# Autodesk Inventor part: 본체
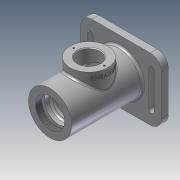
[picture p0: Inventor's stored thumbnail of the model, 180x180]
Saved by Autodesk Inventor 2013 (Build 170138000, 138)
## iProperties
Created: 2021-07
Part Number: 본체
Material: 알루미늄 6061
Document SubType Name: Modeling
Designer: 19
Density: 2.71 g/cm^3
Mass: 742.646 g
Surface Area: 651.172 cm^2
Volume: 274.039 cm^3
Author: 19
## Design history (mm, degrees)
sketch "스케치1"
  geometry: L1 (-57.5, 0)-(57.5, 0); L2 (-57.5, 0)-(-57.5, 31); L3 (-57.5, 31)-(57.5, 31); L4 (57.5, 31)-(57.5, 0); L5 (-57.5, 21)-(-48.5, 21); L6 (-48.5, 21)-(-48.5, 24); L7 (-48.5, 24)-(-45.5, 24); L8 (-45.5, 24)-(-45.5, 20); L9 (-45.5, 20)-(-36.5, 20); L10 (-36.5, 20)-(-36.5, 17.5); L11 (-36.5, 17.5)-(-33.25, 17.5); L12 (-33.25, 17.5)-(-33.25, 18.5); L13 (-33.25, 18.5)-(-31.5, 18.5); L14 (-31.5, 18.5)-(-31.5, 17.5); L15 (-31.5, 17.5)-(-20.5, 17.5); L16 (-20.5, 17.5)-(-20.5, 26); L17 (-20.5, 26)-(17.5, 26); L18 (17.5, 26)-(17.5, 17.5); L19 (17.5, 17.5)-(28.5, 17.5); L20 (28.5, 17.5)-(28.5, 16); L21 (28.5, 16)-(33.5, 16); L22 (33.5, 16)-(33.5, 10); L23 (33.5, 10)-(36.2, 10); L24 (36.2, 10)-(36.2, 12.5); L25 (36.2, 12.5)-(43.5, 12.5); L26 (43.5, 12.5)-(57.5, 22); 2 further points
  constraints: 52 end point, 12 parallel, 12 perpendicular, 2 point on line, 1 coincident, 1 horizontal, 1 midpoint
  dimensions: "d0" = 115 distance of L1.start L1.end; "d1" = 62 diameter of L3 L1; "d2" = 9 distance of L5.start L5.end; "d3" = 3 distance of L6.end L7.end; "d4" = 9 distance of L8.end L9.end; "d5" = 38 distance of L16.end L17.end; "d6" = 11 distance of L14.end L15.end; "d7" = 11 distance of L18.end L19.end; "d8" = 1.75 distance of L12.end L13.end; "d9" = 65 distance of L19.end L10.end; "d10" = 91 horizontal distance of L21.end L5.start; "d11" = 14 horizontal distance of L25.end L26.end; "d12" = 7.3 distance of L24.end L25.end; "d13" = 42 diameter of L5 L1; "d14" = 40 diameter of L9 L1; "d15" = 48 diameter of L7 L1; "d16" = 35 diameter of L15 L1; "d17" = 35 diameter of L11 L1; "d18" = 37 diameter of L13 L1; "d19" = 52 diameter of L17 L1; "d20" = 35 diameter of L19 L1; "d21" = 32 diameter of L21 L1; "d22" = 20 diameter of L23 L1; "d23" = 25 diameter of L25 L1; "d24" = 44 diameter of L26.end L1
revolve "회전1" sketch "스케치1" stored, may be unused: angle "d25" = 90 deg
node "작업 평면1"
sketch "스케치2"
  geometry: L1 (-58, 45)-(58, 45); L2 (58, 45)-(58, -45); L3 (58, -45)-(-58, -45); L4 (-58, -45)-(-58, 45); L5 (-58, 45)-(58, -45); L6 (58, 45)-(-58, -45); C1 r 31 at (0, 0) reference; 1 further point
  constraints: 12 end point, 2 midpoint, 2 parallel, 1 horizontal, 1 perpendicular
  dimensions: "d27" = 116 distance of L2.end L3.end; "d28" = 90 distance of L1.end L2.end
extrude "돌출1" join sketch "스케치2" distance "d29" = 10; taper "d30" = 0 deg
sketch "스케치3"
  geometry: C1 r 31 at (0, 0) reference; C2 r 35 at (0, 0)
  constraints: 1 centre point, 1 coincident
  dimensions: "d31" = 70 diameter of C2
extrude "돌출2" join sketch "스케치3" stored distance "d32" = 10; taper "d33" = 0 deg
fillet "모깎기1" dims "d34" = 16
sketch "스케치4"
  geometry: L1 (40, 25)-(40, -25); L2 (48, -25)-(48, 25); C1 r 35 at (0, 0) reference; A1 r 4 centre (44, 25) between (40, 25) and (48, 25); A2 r 4 centre (44, -25) between (40, -25) and (48, -25)
  constraints: 4 end point, 4 point on circle, 3 tangent, 2 centre point, 1 parallel
  dimensions: "d35" = 8 diameter of A1; "d36" = 8 diameter of A2; "d37" = 50 distance of A2.centre A1.centre; "d38" = 44 horizontal distance of C1.centre A1.centre; "d39" = 25 vertical distance of A1.centre C1.centre; "d40" = 25 vertical distance of C1.centre A2.centre
extrude "돌출3" cut sketch "스케치4" stored distance "d41" = 10; taper "d42" = 0 deg
node "작업 평면2"
sketch "스케치5"
  geometry: L1 (57.5, 31)-(57.5, -31) reference; L2 (57.5, 31)-(-44.5, 31) reference; C1 r 27 at (1.5, 0); 1 further point
  constraints: 1 centre point, 1 coincident
  dimensions: "d44" = 54 diameter of C1; "d81" = 56 distance from line of L1 point (1.5, 0); "d82" = 31 distance from line of L2 point (1.5, 0)
extrude "돌출4" join sketch "스케치5" stored distance "d45" = 10; taper "d46" = 0 deg
sketch "스케치6"
  geometry: C1 r 27 at (0, 0) reference; C2 r 16 at (0, 0)
  constraints: 1 centre point, 1 coincident
  dimensions: "d47" = 32 diameter of C2
extrude "돌출5" cut sketch "스케치6" stored distance "d49" = 10; taper "d50" = 0 deg
sketch "스케치7"
  geometry: L1 (0, 0)-(0, 22); L2 (0, 0)-(0, -22); C1 r 27 at (0, 0) reference; 2 further points
  constraints: 4 end point, 2 coincident, 1 collinear, 1 vertical
  dimensions: "d51" = 22 distance of L1.start L1.end; "d52" = 22 distance of L1.start L2.end
hole "구멍1" sketch "스케치7" at (0, 22), (0, -22) diameter "d53" = 2.459; stored, may be unused: countersink angle "d57" = 90 deg, drill point angle "d59" = 118 deg; dims "d54" = 6, "d55" = 4, "d56" = 2, "d58" = 8
fillet "모깎기2" dims "d60" = 3
feature "스레드1" dims "d61" = 10, "d62" = 0
node "작업 평면3"
sketch "스케치8"
  geometry: L1 (-28.5, 42)-(25.5, 42) reference; 2 further points
  constraints: 1 vertical alignment, 1 other
  dimensions: "d64" = 8 distance from line of L1 point (0, 34)
feature "엠보싱1" sketch "스케치8" dims "d3" = 3, "d65" = 0.5, "d66" = 0
chamfer "모따기1" distance "d67" = 1; stored, may be unused: second distance "d68" = 2, angle "d69" = 45 deg
fillet "모깎기3" dims "d70" = 0.3
fillet "모깎기4" dims "d71" = 0.3
chamfer "모따기3" distance "d76" = 0.7; stored, may be unused: second distance "d77" = 2, angle "d78" = 45 deg
fillet "모깎기6" dims "d79" = 3
fillet "모깎기7" dims "d80" = 3
fillet "모깎기8" dims "d83" = 3
node "솔리드1"
mirror "대칭1"
other parameters: "d26" = -3, "d43" = 42
